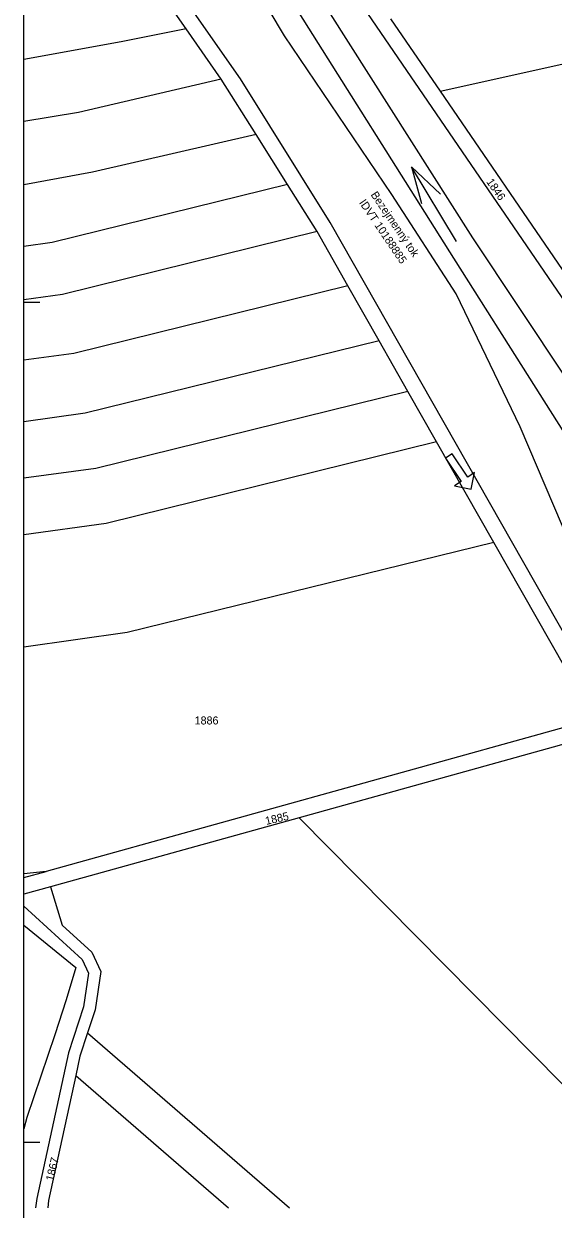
# Model space of a CAD drawing. Extents: x -601754 to -601440, y -1201912 to -1200862.
# Drawn here: x -601751.6 to -601619.2, y -1201719 to -1201422.6 of the extents above; entities that cross this region are included whole.
import ezdxf

# ---------------------------------------------------------------- set-up
doc = ezdxf.new("R2010")
doc.units = 0
for name, color, linetype in [('Hranice parcel', 7, 'Continuous'), ('Parcelní čísla', 7, 'Continuous'), ('u_prijezd', 7, 'Continuous'), ('u_S0 02', 7, 'Continuous'), ('x_rám', 7, 'Continuous')]:
    doc.layers.add(name, color=color, linetype=linetype)

msp = doc.modelspace()

# ---------------------------------------------------------------- linework, layer by layer
at = {"layer": 'Hranice parcel'}
for p, q in [((-601710.99, -1201423.9), (-601720.3, -1201410.62)), ((-601647.48, -1201439.51), (-601517.31, -1201410.46)), ((-601659.87, -1201421.39), (-601647.48, -1201439.51)), ((-601702.19, -1201436.47), (-601710.99, -1201423.9)), ((-601693.43, -1201450.31), (-601702.19, -1201436.47)), ((-601647.48, -1201439.51), (-601615.9, -1201485.66)), ((-601685.59, -1201462.86), (-601693.43, -1201450.31)), ((-601678.24, -1201474.63), (-601685.59, -1201462.86)), ((-601670.53, -1201488.18), (-601678.24, -1201474.63)), ((-601662.72, -1201501.91), (-601670.53, -1201488.18)), ((-601655.53, -1201514.55), (-601662.72, -1201501.91)), ((-601648.34, -1201527.2), (-601655.53, -1201514.55)), ((-601634.01, -1201552.38), (-601648.34, -1201527.2)), ((-601611.88, -1201591.29), (-601634.01, -1201552.38)), ((-601682.69, -1201621.14), (-601744.91, -1201638.42)), ((-601751.58, -1201636.13), (-601745.98, -1201634.57)), ((-601744.91, -1201638.42), (-601751.58, -1201640.28))]:
    msp.add_line(p, q, dxfattribs=at)
for points in [[(-601751.58, -1201306.17), (-601748.76, -1201310.71), (-601730.19, -1201336.75), (-601687.14, -1201388.63), (-601598.97, -1201517.51), (-601569.38, -1201585.08), (-601570.68, -1201592.44)], [(-601751.58, -1201308.71), (-601750.14, -1201311.05), (-601736.9, -1201330.72), (-601724.62, -1201347.71), (-601680.65, -1201411.14), (-601639.4, -1201476.17), (-601592.66, -1201546.3), (-601570.68, -1201592.44)], [(-601751.58, -1201320.86), (-601739.65, -1201337.67), (-601723.67, -1201361.08), (-601684.22, -1201417.67), (-601645.08, -1201479.64), (-601599.95, -1201551.04), (-601577.91, -1201595.98)], [(-601602.51, -1201597.25), (-601612.76, -1201557.83), (-601627.47, -1201523.39), (-601643.42, -1201490.21), (-601659.52, -1201465.35), (-601686.41, -1201425.71), (-601706.32, -1201392.22), (-601751.58, -1201329.34)], [(-601602.51, -1201597.25), (-601606.61, -1201592.45), (-601674.97, -1201472.32), (-601697.36, -1201436.46), (-601751.58, -1201359.05)], [(-601602.51, -1201597.25), (-601606.61, -1201592.45), (-601674.97, -1201472.32), (-601697.36, -1201436.46), (-601751.58, -1201359.05)], [(-601710.99, -1201423.9), (-601727.23, -1201427.21), (-601751.58, -1201431.59)], [(-601702.19, -1201436.47), (-601737.88, -1201444.87), (-601751.58, -1201447.13)], [(-601693.43, -1201450.31), (-601734.41, -1201459.79), (-601751.58, -1201462.93)], [(-601685.59, -1201462.86), (-601744.5, -1201477.31), (-601751.58, -1201478.3)], [(-601678.24, -1201474.63), (-601741.89, -1201490.33), (-601751.58, -1201491.65)], [(-601670.53, -1201488.18), (-601739.07, -1201505.08), (-601751.58, -1201506.79)], [(-601662.72, -1201501.91), (-601736.21, -1201520.04), (-601751.58, -1201522.14)], [(-601655.53, -1201514.55), (-601733.58, -1201533.81), (-601751.58, -1201536.27)], [(-601648.34, -1201527.2), (-601730.95, -1201547.58), (-601751.58, -1201550.4)], [(-601634.01, -1201552.38), (-601725.71, -1201574.86), (-601751.58, -1201578.51)], [(-601611.88, -1201591.29), (-601614.69, -1201598.11), (-601745.98, -1201634.57)], [(-601603.77, -1201605.53), (-601612.65, -1201601.69), (-601682.69, -1201621.14)], [(-601682.69, -1201621.14), (-601595.16, -1201709.69), (-601586.27, -1201718.68)], [(-601745.98, -1201634.57), (-601751.58, -1201635.17)], [(-601744.91, -1201638.42), (-601741.96, -1201647.98), (-601734.51, -1201654.77), (-601732.29, -1201659.59), (-601733.74, -1201669.16), (-601735.62, -1201674.91)], [(-601751.58, -1201643.28), (-601736.98, -1201656.58), (-601735.39, -1201660.03), (-601736.67, -1201668.46), (-601740.42, -1201679.95), (-601748.32, -1201716.37), (-601748.61, -1201718.68)], [(-601751.58, -1201648.03), (-601738.53, -1201658.62), (-601741.01, -1201666.68), (-601743.78, -1201675.46), (-601750.84, -1201696.06), (-601751.58, -1201698.94)], [(-601735.62, -1201674.91), (-601737.52, -1201680.74), (-601738.57, -1201685.58)], [(-601735.62, -1201674.91), (-601685.14, -1201718.68)], [(-601738.57, -1201685.58), (-601745.36, -1201716.88), (-601745.59, -1201718.68)], [(-601738.57, -1201685.58), (-601700.4, -1201718.68)]]:
    msp.add_lwpolyline(points, dxfattribs=at)
at = {"layer": 'u_prijezd'}
msp.add_lwpolyline([(-601643.89, -1201538.21), (-601639.73, -1201539.04), (-601638.9, -1201534.88), (-601640.56, -1201535.99), (-601644.45, -1201530.17), (-601646.12, -1201531.28), (-601642.23, -1201537.1), (-601643.89, -1201538.21)], dxfattribs=at)
at = {"layer": 'u_S0 02'}
for p, q in [((-601643.37, -1201477.06), (-601654.62, -1201458.39)), ((-601654.62, -1201458.39), (-601652.14, -1201467.61)), ((-601654.62, -1201458.39), (-601647.41, -1201465.25))]:
    msp.add_line(p, q, dxfattribs=at)
at = {"layer": 'x_rám'}
for p, q in [((-601747.54, -1201492.35), (-601751.58, -1201492.35)), ((-601747.54, -1201702.35), (-601751.58, -1201702.35))]:
    msp.add_line(p, q, dxfattribs=at)
msp.add_lwpolyline([(-601454.58, -1200862.35), (-601454.58, -1201912.35), (-601751.58, -1201912.35), (-601751.58, -1200862.35)], close=True, dxfattribs=at)

# ---------------------------------------------------------------- texts
at = {"layer": 'Parcelní čísla'}
for s, rotation, p in [('1846', 305, (-601636.01, -1201462.18)), ('1885', 13, (-601690.94, -1201622.96)), ('1867', 76, (-601744.19, -1201712.13))]:
    msp.add_text(s, height=2, rotation=rotation, dxfattribs=at).set_placement(p)
msp.add_text('1886', height=2, dxfattribs=at).set_placement((-601708.84, -1201597.83))
at = {"layer": 'u_S0 02'}
for s, p in [('Bezejmenný tok', (-601664.91, -1201465.41)), ('IDVT 10188885', (-601667.81, -1201467.38))]:
    msp.add_text(s, height=2, rotation=304.1729, dxfattribs=at).set_placement(p)

doc.saveas('drawing.dxf')
